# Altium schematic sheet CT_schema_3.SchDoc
size 187 x 169 mm
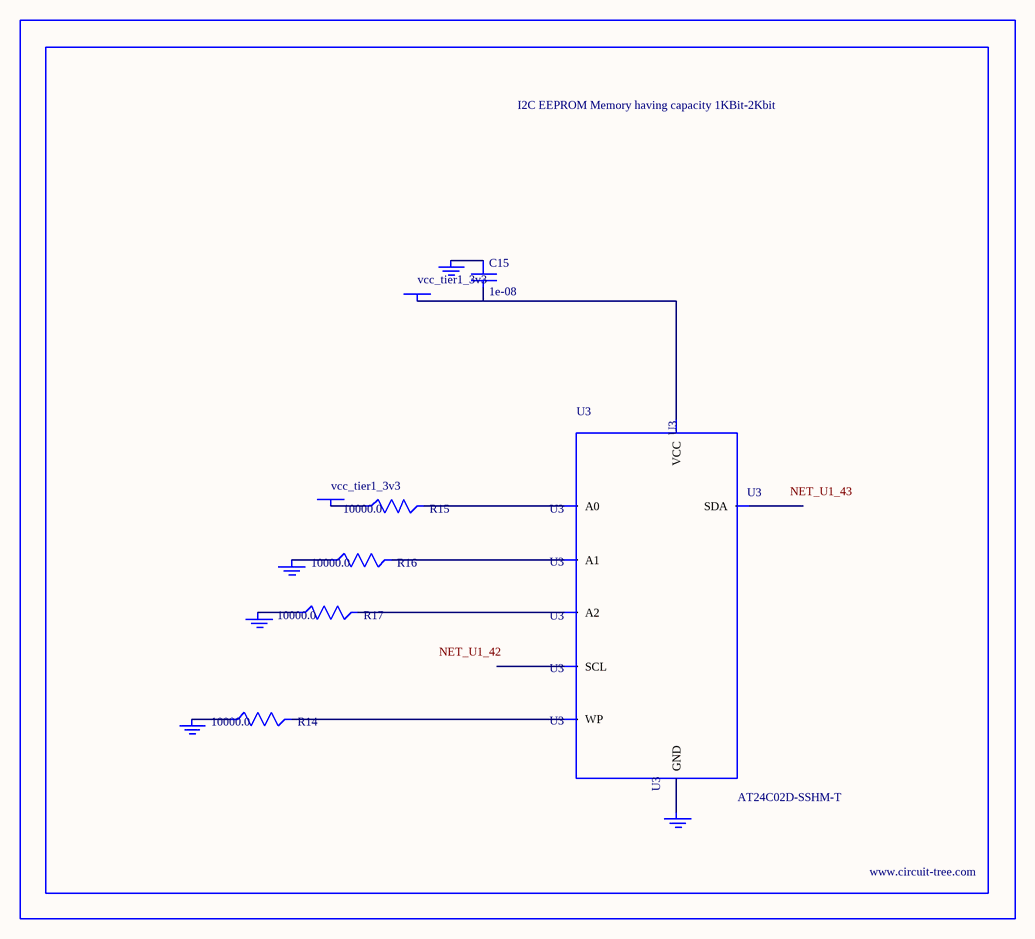
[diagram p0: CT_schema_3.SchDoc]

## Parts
BORDER2  (no value)
C15  1e-08  [C0402]
GND_INSTANCE_2_0  (no value)
GND_INSTANCE_2_1  (no value)
GND_INSTANCE_2_2  (no value)
GND_INSTANCE_2_3  (no value)
GND_INSTANCE_2_4  (no value)
POWER_INSTANCE_2_0  vcc_tier1_3v3
POWER_INSTANCE_2_1  vcc_tier1_3v3
R14  10000.0  [R0603]
R15  10000.0  [R0603]
R16  10000.0  [R0603]
R17  10000.0  [R0603]
U3  AT24C02D-SSHM-T  [AT24C02D]

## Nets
NetC15_1: C15.1 GND_INSTANCE_2_3.0(GND)
NetC15_2: C15.2 POWER_INSTANCE_2_1.0(PWR) U3.8(VCC)
NetGND_INSTANCE_2_0_0: GND_INSTANCE_2_0.0(GND) R16.1
NetGND_INSTANCE_2_1_0: GND_INSTANCE_2_1.0(GND) R17.1
NetGND_INSTANCE_2_2_0: GND_INSTANCE_2_2.0(GND) R14.1
NetGND_INSTANCE_2_4_0: GND_INSTANCE_2_4.0(GND) U3.4(GND)
NetPOWER_INSTANCE_2_0_0: POWER_INSTANCE_2_0.0(PWR) R15.1
NetR14_2: R14.2 U3.7(WP)
NetR15_2: R15.2 U3.1(A0)
NetR16_2: R16.2 U3.2(A1)
NetR17_2: R17.2 U3.3(A2)

Not connected (* = marked no-connect by the designer): U3 5(SDA) 6(SCL)

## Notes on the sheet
- Labels drawn without touching a wire or pin: NET_U1_42, NET_U1_43

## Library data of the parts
BORDER2 = BORDER_PAGE2
C15 = C0402C103K3RAC
GND_INSTANCE_2_0-GND_INSTANCE_2_4 = GND
POWER_INSTANCE_2_0 POWER_INSTANCE_2_1 = PWR
R14-R17 = RC0603JR-0710KL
